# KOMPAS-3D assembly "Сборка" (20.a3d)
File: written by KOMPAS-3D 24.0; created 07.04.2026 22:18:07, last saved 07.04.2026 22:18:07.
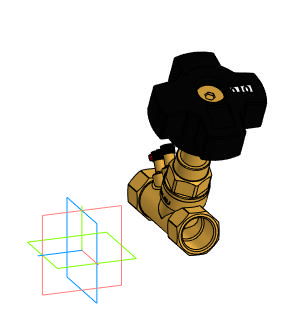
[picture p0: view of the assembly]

Document properties: Автор: tyuri; Полное имя файла: D:\Аутсорс\VB0000P-T Клапан балансировочный статический DN.ru\DN20\Исходные файлы\20.a3d

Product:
- Component [detail]: Деталь1  | qty 1  | Автор: tyuri; source file: Деталь1 - Деталь1.m3d
- Component [detail]: Деталь2  | qty 1  | Автор: tyuri; source file: Деталь2 - Деталь2.m3d
- Part/product: Сборка

Referenced files in D:\Аутсорс\VB0000P-T Клапан балансировочный статический DN.ru\DN20\Исходные файлы\: Деталь1 - Деталь1.m3d, Деталь2 - Деталь2.m3d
